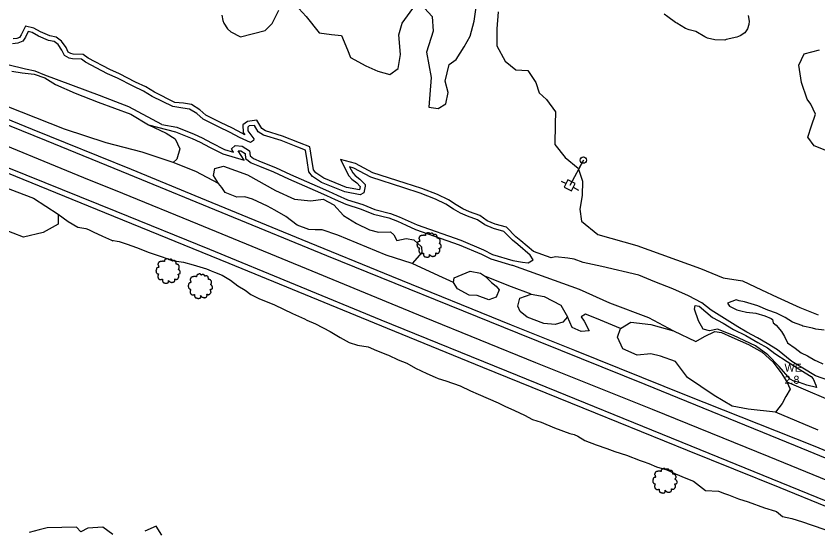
# Model space of a CAD drawing. Extents: x 2160437 to 2172832, y 205694 to 212444.
# Drawn here: x 2165285 to 2165786, y 209408 to 209730 of the extents above; entities that cross this region are included whole.
import ezdxf

# ---------------------------------------------------------------- set-up
doc = ezdxf.new("R2010")
doc.units = 0
for name, color, linetype in [('RD_EX_H2O', 7, 'Continuous'), ('RD_EX_H2O_Pond', 7, 'Continuous'), ('RD_EX_H2O_txCode', 7, 'Continuous'), ('RD_EX_LaneStripe', 7, 'Continuous'), ('RD_EX_Road', 7, 'Continuous'), ('RD_EX_UT', 7, 'Continuous'), ('RD_EX_UT_Guy', 7, 'Continuous'), ('RD_EX_VEG', 7, 'Continuous'), ('RD_EX_VEG_ShrubLine', 7, 'Continuous'), ('RD_EX_VEG_TreeLine', 7, 'Continuous')]:
    doc.layers.add(name, color=color, linetype=linetype)

# ---------------------------------------------------------------- blocks, each defined once
blk = doc.blocks.new('T2')
at = {"layer": 'RD_EX_VEG'}
for points in [[(0.05, 7.21), (-0.25, 7.24), (-0.57, 7.14), (-0.82, 7.04), (-1.05, 6.96), (-1.27, 6.86), (-1.57, 6.69), (-1.8, 6.49), (-1.92, 6.24), (-1.97, 6.01), (-2.02, 5.74), (-2.02, 5.56), (-2.15, 5.54), (-2.3, 5.56), (-2.55, 5.64), (-2.8, 5.64), (-3.05, 5.64), (-3.4, 5.61), (-3.75, 5.61), (-4.02, 5.56), (-4.35, 5.51), (-4.72, 5.39), (-5.07, 5.26), (-5.37, 5.01), (-5.62, 4.54), (-5.75, 4.19), (-5.9, 3.94), (-5.75, 3.49), (-5.57, 3.14), (-5.55, 2.94), (-5.47, 2.52), (-5.37, 2.29), (-5.25, 2.09), (-5.32, 2.07), (-5.7, 2.02), (-6, 1.92), (-6.42, 1.69), (-6.64, 1.47), (-6.74, 1.14), (-6.77, 0.79), (-6.87, 0.59), (-6.94, 0.32), (-6.97, 0.24), (-7.02, -0.08), (-6.92, -0.53), (-6.89, -0.88), (-6.77, -1.11), (-6.62, -1.28), (-6.44, -1.53), (-6.05, -1.76), (-5.72, -1.86), (-5.52, -1.88), (-5.7, -2.38), (-5.75, -2.73), (-5.87, -3.13), (-5.87, -3.21), (-5.92, -3.68), (-5.77, -4.01), (-5.7, -4.38), (-5.52, -4.61), (-5.25, -4.91), (-4.92, -5.13), (-4.42, -5.26), (-4.02, -5.23), (-3.45, -5.06), (-3.2, -4.98), (-3.22, -5.16), (-3.2, -5.53), (-3.2, -5.96), (-3.05, -6.28), (-2.95, -6.56), (-2.8, -6.81), (-2.47, -7.03), (-2.07, -7.11), (-1.65, -7.26), (-1.2, -7.33), (-0.7, -7.36), (-0.1, -7.21), (0.18, -7.08), (0.28, -6.91), (0.48, -6.53), (0.43, -6.31), (0.45, -5.71), (0.55, -5.88), (0.73, -6.23), (1.23, -6.53), (1.63, -6.71), (2.1, -6.86), (2.4, -6.93), (2.88, -6.86), (3.25, -6.78), (3.63, -6.66), (3.93, -6.38), (4.1, -6.11), (4.15, -5.83), (4.23, -5.46), (4.28, -5.28)], [(4.28, -5.28), (4.2, -5.11), (4.15, -4.86), (4.23, -4.88), (4.4, -4.93), (4.68, -5.06), (4.9, -5.13), (5.23, -5.11), (5.5, -5.01), (5.95, -4.73), (6.22, -4.26), (6.5, -3.86), (6.57, -3.53), (6.52, -3.31), (6.5, -2.81), (6.3, -2.56), (6.25, -2.43), (6.15, -2.03), (6.22, -1.98), (6.5, -1.93), (6.87, -1.81), (7.15, -1.68), (7.37, -1.51), (7.45, -1.28), (7.42, -0.88), (7.47, -0.48), (7.4, -0.33), (7.3, -0.18), (7.22, 0.02), (7.07, 0.17), (6.97, 0.32), (6.87, 0.42), (6.75, 0.57), (6.57, 0.69), (6.42, 0.74), (6.37, 0.89), (6.52, 1.09), (6.57, 1.19), (6.6, 1.42), (6.82, 1.77), (6.87, 2.17), (6.82, 2.59), (6.77, 2.87), (6.62, 3.14), (6.42, 3.39), (6.3, 3.56), (6.12, 3.69), (5.8, 3.81), (5.55, 3.86), (5.2, 3.86), (5, 3.91), (5.03, 3.96), (5.03, 4.11), (5.03, 4.39), (4.95, 4.84), (4.8, 5.34), (4.8, 5.36), (4.7, 5.61), (4.48, 5.81), (4.3, 5.91), (4.1, 6.04), (3.85, 6.06), (3.55, 6.06), (3.28, 6.01), (3.08, 5.91), (2.9, 5.79), (2.83, 5.94), (2.73, 6.24), (2.68, 6.39), (2.53, 6.56), (2.3, 6.76), (1.85, 6.89), (1.23, 6.81), (0.93, 6.61), (0.78, 6.44), (0.73, 6.56), (0.53, 6.76), (0.43, 6.94), (0.25, 7.06), (0.1, 7.16), (0, 7.21)]]:
    blk.add_spline(points, degree=3, dxfattribs=at)
blk = doc.blocks.new('PP')
at = {"layer": 'RD_EX_UT'}
for p, q in [((2.49, 2.51), (-2.51, 2.51)), ((-2.51, 2.51), (-2.51, -2.49)), ((2.49, -2.49), (2.49, 2.51)), ((-5.94, -0.05), (-2.47, -0.05)), ((-2.51, -2.49), (2.49, -2.49)), ((2.42, -0.05), (6.06, -0.05))]:
    blk.add_line(p, q, dxfattribs=at)

msp = doc.modelspace()

# ---------------------------------------------------------------- linework, layer by layer
at = {"layer": 'RD_EX_H2O'}
for points in [[(2165383.21, 209673.19), (2165370.29, 209679.52), (2165364.87, 209682.85), (2165358.5, 209685.91), (2165348.6, 209690.96), (2165342.47, 209693.62), (2165328.63, 209700.92), (2165326.12, 209702.91), (2165320.55, 209703.04), (2165318.44, 209703.55), (2165315.57, 209705.19), (2165313.96, 209708.57), (2165311.53, 209711.95), (2165309.1, 209713.84), (2165305.53, 209714.5), (2165299.28, 209717.18), (2165295.27, 209719.47), (2165292.87, 209720.08), (2165291.13, 209716.69), (2165289.58, 209714.02), (2165286.45, 209712.89), (2165283.09, 209712.55)], [(2165376.36, 209662.08), (2165355.65, 209673.06), (2165347.65, 209676.25), (2165337.34, 209680.16), (2165303.22, 209692.96), (2165297.17, 209695.4), (2165291.1, 209696.71), (2165280.11, 209699.37)], [(2165376.36, 209662.08), (2165385.62, 209660.32), (2165396.5, 209656.08), (2165401.61, 209653.67), (2165407.42, 209650.5), (2165415.52, 209646.44), (2165421.12, 209644.82), (2165420.11, 209646.45), (2165419.78, 209646.92), (2165422.09, 209648.84), (2165426.52, 209648.5), (2165431.17, 209645.67), (2165431.43, 209642.37), (2165433.62, 209640.76), (2165438.4, 209638.73), (2165447.29, 209635.23), (2165456.69, 209630.73), (2165473.41, 209623.58), (2165480.41, 209620.42), (2165485.75, 209617.82), (2165492.31, 209614.99), (2165501.79, 209612), (2165509.44, 209608.97), (2165519.06, 209606.51), (2165524.64, 209604.35), (2165530.19, 209601.79), (2165535.87, 209599.26), (2165563.11, 209589.7), (2165577.29, 209583.8), (2165582.91, 209580.9), (2165595.64, 209577.06), (2165601.64, 209575.94), (2165605.02, 209575.66), (2165608.17, 209577.53), (2165606.29, 209580.46), (2165598.59, 209586.97), (2165595.31, 209589.7), (2165590.01, 209595.14), (2165583.51, 209596.98), (2165577.95, 209599.28), (2165573.45, 209602.55), (2165567.29, 209604.74), (2165562.93, 209606.68), (2165558.5, 209609.19), (2165553.79, 209612.28), (2165547.22, 209615.48), (2165537.61, 209619.11), (2165527.37, 209622.44), (2165506.92, 209629.07), (2165496.22, 209634.83), (2165493.57, 209635.51), (2165495.52, 209631.74), (2165497.01, 209630.17), (2165500.01, 209627.83), (2165503.38, 209624.47), (2165503.41, 209623.51), (2165502.46, 209619.25), (2165500.27, 209617.99), (2165490.71, 209619.88), (2165476.09, 209625.83), (2165470.37, 209629.51), (2165468.17, 209632.54), (2165467.1, 209639.64), (2165466.08, 209645.92), (2165461.28, 209647.91), (2165450.8, 209652.02), (2165439.87, 209655.43), (2165436.58, 209657.44), (2165434.11, 209661.49), (2165430.95, 209661.12), (2165429.96, 209660.42), (2165430.14, 209658.07), (2165433.79, 209653), (2165433.58, 209652), (2165431.7, 209650.75), (2165424.87, 209653.87), (2165419.09, 209657.12), (2165411.68, 209660.6), (2165402.1, 209665.31), (2165398.17, 209668.83), (2165393.71, 209671.67), (2165389.37, 209672.33), (2165383.21, 209673.19)]]:
    msp.add_lwpolyline(points, dxfattribs=at)
at = {"layer": 'RD_EX_H2O_Pond'}
msp.add_lwpolyline([(2165768.77, 209502.88), (2165761.78, 209510.76), (2165754.88, 209518.14), (2165747.12, 209523.77), (2165733.39, 209530.1), (2165723.32, 209534.12), (2165718.28, 209533.09), (2165714.35, 209534.06), (2165711.58, 209539.38), (2165709.08, 209546.63), (2165709.42, 209548.93), (2165711.93, 209548.45), (2165720.24, 209541.49), (2165726.87, 209537.9), (2165733.4, 209534), (2165740.95, 209530.14), (2165748.47, 209525.8), (2165754.62, 209522.57), (2165759.26, 209519), (2165766.77, 209514.03), (2165775.39, 209508.57), (2165781.75, 209504.6), (2165783.09, 209503.1), (2165784.83, 209499.05), (2165785.27, 209497.68), (2165779.14, 209499.22), (2165774.54, 209500.72), (2165771.03, 209501.74)], close=True, dxfattribs=at)
at = {"layer": 'RD_EX_LaneStripe'}
for points in [[(2164713.96, 209878.5), (2164761.8, 209859.02), (2164833.01, 209830.23), (2164905.18, 209800.77), (2164974.57, 209772.6), (2165045.57, 209743.73), (2165114.59, 209715.4), (2165186.42, 209686.18), (2165257.45, 209657.65), (2165327.49, 209628.98), (2165351.71, 209619.17)], [(2165351.71, 209619.17), (2165398.66, 209599.89), (2165469.92, 209570.6), (2165540.18, 209541.69), (2165609.74, 209513.4), (2165682.5, 209484.08), (2165755.38, 209454.5), (2165825.21, 209425.99), (2165895.04, 209397.29), (2165966.21, 209368.17), (2166025.36, 209344.25)]]:
    msp.add_lwpolyline(points, dxfattribs=at)
at = {"layer": 'RD_EX_Road'}
for points in [[(2164719.32, 209893.53), (2164801.13, 209860.4), (2164852.34, 209839.67), (2164925.53, 209809.88), (2165006.4, 209777.19), (2165079.44, 209747.05), (2165147.78, 209719.5), (2165223.63, 209688.47), (2165295.33, 209659.22), (2165357.09, 209634.04)], [(2165355.66, 209630.84), (2165304.42, 209651.77), (2165236.8, 209679.06), (2165166.59, 209707.41), (2165107.77, 209731.24), (2165033.8, 209761.44), (2164971.08, 209787.01), (2164897.12, 209817.11), (2164827.21, 209845.74), (2164717.47, 209890.02)], [(2165346.3, 209604.56), (2165269.06, 209635.97), (2165210.92, 209659.39), (2165137.15, 209689.5), (2165059.95, 209721.27), (2164996.92, 209746.76), (2164929.74, 209773.98), (2164862.92, 209800.29), (2164815.46, 209819.83), (2164749.27, 209847.18), (2164706.89, 209864.18)], [(2164708.26, 209867.65), (2164791.22, 209833.73), (2164881.75, 209797.03), (2164973.9, 209759.85), (2165049.76, 209728.91), (2165135.66, 209693.84), (2165203.67, 209666.14), (2165280.55, 209635.01), (2165347.69, 209607.9)], [(2165357.09, 209634.04), (2165400.48, 209616.17), (2165463.79, 209590.16), (2165519.82, 209567.3), (2165594.5, 209536.83), (2165634.04, 209521.03), (2165703.73, 209492.82), (2165783.1, 209461.45), (2165877.48, 209422.45), (2165937.8, 209397.18), (2165998.2, 209372.29), (2166026.17, 209360.72)], [(2166024.71, 209357.76), (2165943.48, 209390.77), (2165859.72, 209425.24), (2165772.07, 209461.29), (2165678.08, 209499.62), (2165598.61, 209531.58), (2165479.36, 209579.95), (2165355.66, 209630.84)], [(2165347.69, 209607.9), (2165406.01, 209584.16), (2165513.05, 209539.94), (2165598.18, 209505.37), (2165706.73, 209461.26), (2165813.54, 209417.73), (2165902.46, 209381.16), (2166015.83, 209334.81)], [(2166014.65, 209331.72), (2165949.69, 209358.32), (2165878.21, 209387.6), (2165819.58, 209411.66), (2165762.4, 209434.9), (2165704.62, 209458.26), (2165647.21, 209481.6), (2165576.85, 209510.24), (2165517.3, 209534.48), (2165418.35, 209575.15), (2165346.3, 209604.56)]]:
    msp.add_lwpolyline(points, dxfattribs=at)
at = {"layer": 'RD_EX_UT'}
msp.add_line((2165639.58, 209639.79), (2165637.26, 209635.36), dxfattribs=at)
msp.add_circle((2165639.58, 209639.79), 2, dxfattribs=at)
at = {"layer": 'RD_EX_UT_Guy'}
msp.add_lwpolyline([(2165639.58, 209639.79), (2165631.1, 209623.97)], dxfattribs=at)
at = {"layer": 'RD_EX_VEG_ShrubLine'}
for points in [[(2165413.87, 209730.4), (2165414.42, 209727.04), (2165414.96, 209725.3), (2165417.33, 209721.86), (2165419.36, 209719.94), (2165425.49, 209716.74), (2165425.49, 209716.74), (2165440.97, 209720.85), (2165445.27, 209725.21), (2165449.35, 209733.57)], [(2165459.57, 209736.93), (2165466.52, 209729.48), (2165474.53, 209719.29), (2165482.38, 209718.34), (2165488.58, 209717.59), (2165492.22, 209708.61), (2165494.25, 209703.98), (2165503.71, 209698.69), (2165511.3, 209695.31), (2165518.83, 209693.24), (2165524, 209697.12), (2165525.32, 209705.8), (2165524.31, 209718.06), (2165526.4, 209725.4), (2165533.04, 209734.62)], [(2165540.39, 209734.8), (2165545.09, 209729.63), (2165545.73, 209720.44), (2165541.53, 209707.32), (2165544.55, 209691.44), (2165543.16, 209672.97), (2165548.89, 209671.97), (2165553.63, 209674.86), (2165555.16, 209681.99), (2165553.32, 209689.08), (2165555.75, 209699.45), (2165560.1, 209702.7), (2165565.16, 209710.62), (2165568.99, 209717.19), (2165571.35, 209726.58), (2165572.85, 209736.91)], [(2165586.36, 209732.54), (2165585.55, 209721.73), (2165585.54, 209711.28), (2165590.73, 209701.71), (2165597.41, 209696.29), (2165604.9, 209695.77), (2165609.92, 209688.27), (2165612.07, 209681.86), (2165616.65, 209677.65), (2165622.09, 209669.87), (2165621.99, 209662.28), (2165621.79, 209649.56), (2165628.29, 209641.5), (2165636.25, 209634.68), (2165639.04, 209626.63), (2165638.93, 209617.6), (2165637.42, 209609.09), (2165638.43, 209601.55), (2165648.54, 209593.24), (2165672.94, 209586.4), (2165712.72, 209572.07), (2165726.93, 209566.22), (2165738.98, 209564.31), (2165750.76, 209558.71), (2165760.66, 209554.22), (2165774.75, 209547.68), (2165786.14, 209543.07)], [(2165742.46, 209730.18), (2165743.03, 209726.56), (2165742.83, 209724.47), (2165742.05, 209721.91), (2165740.35, 209719.3), (2165737.5, 209717.39), (2165735.53, 209716.63), (2165728.83, 209715.06), (2165727.85, 209714.68), (2165721.74, 209714.85), (2165717.08, 209716.02), (2165715.52, 209716.8), (2165709.8, 209720.07), (2165705.74, 209721.15), (2165703.39, 209722.01), (2165697.86, 209725.29), (2165697.05, 209725.74), (2165692.44, 209729.24), (2165689.97, 209731.06)], [(2165384.53, 209675.88), (2165371.73, 209682.15), (2165366.31, 209685.48), (2165359.83, 209688.6), (2165349.88, 209693.67), (2165343.77, 209696.32), (2165330.28, 209703.45), (2165327.2, 209705.88), (2165320.95, 209706.03), (2165319.56, 209706.37), (2165317.87, 209707.33), (2165316.55, 209710.1), (2165313.71, 209714.06), (2165310.36, 209716.66), (2165306.4, 209717.39), (2165300.62, 209719.86), (2165296.4, 209722.27), (2165291.3, 209723.58), (2165288.49, 209718.13), (2165287.54, 209716.47), (2165285.78, 209715.84), (2165283.44, 209715.6)], [(2165790.5, 209646.07), (2165783.8, 209648.78), (2165779.8, 209654.1), (2165782.01, 209661.11), (2165784.61, 209668.59), (2165781.57, 209674.84), (2165779.39, 209677.9), (2165779.39, 209677.9), (2165775.76, 209688.33), (2165774.22, 209699.19), (2165777.51, 209706.18), (2165787.06, 209708.65)], [(2165805.27, 209497.64), (2165784.63, 209505.04), (2165769.85, 209514.02), (2165760.79, 209521.13), (2165754.44, 209525.14), (2165748.35, 209528.8), (2165741.63, 209532.29), (2165735.98, 209535.62), (2165719.45, 209545.96), (2165713.57, 209550.53), (2165705.31, 209554.93), (2165695.53, 209559.41), (2165684.24, 209563.75), (2165674.2, 209567.84), (2165651.19, 209573.3), (2165639.42, 209575.85), (2165633.86, 209577.96), (2165629.97, 209578.6), (2165622.22, 209579.27), (2165619.39, 209578.72), (2165608.36, 209582.63), (2165600.52, 209589.26), (2165597.35, 209591.9), (2165591.6, 209597.81), (2165584.5, 209599.82), (2165579.42, 209601.91), (2165574.86, 209605.23), (2165568.41, 209607.53), (2165564.28, 209609.36), (2165560.07, 209611.75), (2165555.28, 209614.9), (2165548.41, 209618.24), (2165538.61, 209621.95), (2165528.3, 209625.29), (2165508.11, 209631.84), (2165497.32, 209637.65), (2165487.83, 209640.08), (2165493.05, 209629.98), (2165494.98, 209627.94), (2165498.02, 209625.58), (2165500.29, 209623.32), (2165499.82, 209621.19), (2165499.76, 209621.15), (2165491.57, 209622.77), (2165477.48, 209628.51), (2165472.46, 209631.74), (2165471.03, 209633.71), (2165470.07, 209640.11), (2165468.77, 209648.04), (2165462.41, 209650.69), (2165451.8, 209654.85), (2165441.12, 209658.18), (2165438.76, 209659.62), (2165435.67, 209664.69), (2165429.85, 209664.01), (2165426.84, 209661.9), (2165427.21, 209657), (2165428.18, 209655.66), (2165426.23, 209656.55), (2165420.46, 209659.79), (2165412.98, 209663.3), (2165403.8, 209667.82), (2165399.99, 209671.23), (2165394.79, 209674.54), (2165389.8, 209675.3), (2165384.53, 209675.88)], [(2165368.02, 209661.84), (2165384.79, 209657.43), (2165395.32, 209653.32), (2165400.25, 209651), (2165406.03, 209647.84), (2165414.42, 209643.64), (2165427.75, 209639.77), (2165424.11, 209645.68), (2165425.58, 209645.57), (2165428.3, 209643.91), (2165428.55, 209640.77), (2165432.13, 209638.14), (2165437.26, 209635.95), (2165446.09, 209632.48), (2165455.45, 209628), (2165472.2, 209620.83), (2165479.14, 209617.7), (2165484.5, 209615.09), (2165491.26, 209612.18), (2165500.78, 209609.18), (2165508.51, 209606.11), (2165518.15, 209603.65), (2165523.47, 209601.58), (2165528.95, 209599.06), (2165534.77, 209596.47), (2165562.03, 209586.9), (2165576.02, 209581.08), (2165581.77, 209578.11), (2165594.93, 209574.14), (2165595.27, 209574.07), (2165636.93, 209559.05), (2165655.82, 209550.56), (2165680.17, 209541.47), (2165695.89, 209533.1)], [(2165411.78, 209625.18), (2165397.56, 209632.71), (2165383.48, 209638.33)], [(2165311.58, 209606.05), (2165317.82, 209601.48), (2165323.88, 209597.83), (2165328.8, 209597.03), (2165330.52, 209596.45), (2165333.48, 209595.02), (2165339.2, 209592.24), (2165344.83, 209589.8), (2165345.81, 209589.31)], [(2165344.83, 209589.8), (2165344.83, 209589.8), (2165349.77, 209588.93), (2165354.59, 209587.29), (2165360.61, 209585.2), (2165368.47, 209582.03), (2165376.03, 209579.53), (2165379.49, 209578.31), (2165382.62, 209576.97), (2165389.95, 209575.98), (2165396.01, 209574.28), (2165404.21, 209571.78), (2165407.08, 209570.59), (2165409.24, 209569.72), (2165414.1, 209567.88), (2165419.3, 209564.75), (2165423.81, 209561.29), (2165428.4, 209558.44), (2165431.91, 209555.82), (2165436.95, 209553.36), (2165446.73, 209549.29), (2165457.97, 209544.02), (2165465.43, 209540.56), (2165466.8, 209539.87), (2165472.3, 209537.42), (2165481.47, 209532.61), (2165487.62, 209528.97), (2165493.27, 209525.83), (2165498.44, 209524.17), (2165505.23, 209523.1), (2165510.41, 209520.84), (2165517.31, 209518.19), (2165517.86, 209517.89), (2165523.83, 209515.06), (2165529.39, 209512.86), (2165534.82, 209509.85), (2165541.73, 209506.38), (2165547.14, 209504.25), (2165548.95, 209503.3), (2165553.79, 209501.83), (2165562.58, 209498.7), (2165569.16, 209495.64), (2165573.8, 209493.49), (2165580.22, 209490.77), (2165586.44, 209488.09), (2165590.57, 209485.94), (2165596.51, 209483.25), (2165602.77, 209480.47), (2165607.82, 209477.64), (2165613.28, 209476.12), (2165621.56, 209472.57), (2165631.05, 209468.99), (2165633.93, 209468.3), (2165636.22, 209467.24), (2165640.54, 209464.68), (2165647.67, 209461.92), (2165654.29, 209459.53), (2165659.2, 209457.8), (2165666.46, 209455.34), (2165675.09, 209452.05), (2165677.01, 209451.47), (2165680.56, 209450.16), (2165685.24, 209448.22), (2165691.63, 209446.34), (2165697.17, 209443.78), (2165703.61, 209441.1), (2165708.39, 209439.07), (2165715.86, 209433.29), (2165723.98, 209432.96), (2165727.8, 209431.44), (2165730.29, 209430.7), (2165736.4, 209428.21), (2165742.41, 209426.17), (2165752.63, 209422.4), (2165759.58, 209420.35), (2165760.16, 209420.23), (2165764.04, 209417.1), (2165769.84, 209415.75), (2165776.35, 209413.72), (2165781.86, 209411.81), (2165790.96, 209408.68)], [(2165558.42, 209563.23), (2165549.34, 209567.44), (2165532.75, 209575.18)], [(2165606.97, 209555.96), (2165594.81, 209560.68), (2165578.57, 209567.08)], [(2165790, 209533.45), (2165784.8, 209534.22), (2165782.69, 209534.79), (2165776.65, 209536.11), (2165775.96, 209536.42), (2165770.25, 209538.5), (2165770.25, 209538.5), (2165765.69, 209541.53), (2165760.19, 209544.06), (2165754.82, 209546.09), (2165748.5, 209548.63), (2165740.2, 209551.22), (2165736.79, 209551.92), (2165735.09, 209552.4), (2165729.68, 209550.45), (2165730.92, 209548.53), (2165730.92, 209548.53), (2165735.52, 209546.22), (2165737.93, 209545.69), (2165741.42, 209544.77), (2165747.25, 209544.18), (2165747.25, 209544.18), (2165752.86, 209542.51), (2165756.84, 209540.83), (2165757.8, 209540.13), (2165758.19, 209538.14), (2165759.9, 209536.66), (2165763.27, 209532.79), (2165765.23, 209529.65), (2165767.16, 209525.61), (2165771.85, 209522.26), (2165775.69, 209519.46), (2165779.61, 209517.44), (2165784.08, 209514.82), (2165785.6, 209514.15), (2165789.16, 209512.56)], [(2165662.76, 209534.61), (2165647.88, 209540.86), (2165641.01, 209543.6), (2165638.19, 209541.85), (2165640.02, 209539.13), (2165643.27, 209533.05), (2165638.26, 209532.73), (2165632.65, 209535.23), (2165629.62, 209541.8)], [(2165766.6, 209501.26), (2165802.67, 209485.82)], [(2165786.28, 209471.03), (2165759.49, 209482.3)], [(2165345.82, 209405.85), (2165339.48, 209410.46), (2165330.21, 209409.88), (2165325.77, 209407.44), (2165323.08, 209410.35), (2165304.65, 209409.95), (2165299.84, 209408.75), (2165293.59, 209407.04)], [(2165376.44, 209405.49), (2165372.7, 209410.95), (2165365.69, 209407.89)]]:
    msp.add_lwpolyline(points, dxfattribs=at)
for points in [[(2165442.38, 209610.94), (2165433.04, 209615.37), (2165428.21, 209616.79), (2165423.26, 209616.58), (2165415.92, 209619.57), (2165413.91, 209622.73), (2165411.78, 209625.18), (2165408.67, 209630.15), (2165409.5, 209634.46), (2165414.78, 209635.93), (2165429.8, 209630.57), (2165447.4, 209620.8), (2165459.23, 209615.31), (2165469.48, 209614.25), (2165477.12, 209615.31), (2165483.8, 209611.84), (2165489.85, 209605.11), (2165497.88, 209600.18), (2165506.11, 209596.2), (2165511.68, 209594.73), (2165519.08, 209595.02), (2165521.14, 209593.02), (2165523.06, 209589.57), (2165528.99, 209590.75), (2165533.67, 209590.04), (2165538.59, 209585.67), (2165538.75, 209582.05), (2165532.75, 209575.18), (2165516.44, 209580.3), (2165486.2, 209592.92), (2165476.46, 209596.25), (2165472.01, 209596.14), (2165468.22, 209596.41), (2165460.78, 209599.08), (2165453.73, 209604.49), (2165446.84, 209608.51)], [(2165558.98, 209566.25), (2165568.81, 209570.37), (2165575.35, 209569.24), (2165578.57, 209567.08), (2165582.25, 209563.4), (2165585.13, 209561.08), (2165587.07, 209558.81), (2165585.1, 209554.18), (2165580.46, 209552.52), (2165573.24, 209555.09), (2165568.37, 209555.49), (2165561.08, 209559.32), (2165558.42, 209563.23)], [(2165598.6, 209548.46), (2165600, 209553.47), (2165606.97, 209555.96), (2165615.15, 209554.64), (2165625.51, 209549.22), (2165629.62, 209541.8), (2165626.7, 209538.51), (2165622.05, 209537.03), (2165614.98, 209537.68), (2165604.39, 209541.66), (2165600.13, 209545.27)], [(2165759.49, 209482.3), (2165742.51, 209484.26), (2165732.54, 209486.06), (2165721.28, 209492.61), (2165704.58, 209503.89), (2165697.1, 209513.94), (2165687.76, 209517.36), (2165681.81, 209518.78), (2165673.11, 209517.93), (2165664.27, 209521.95), (2165660.93, 209529.25), (2165662.76, 209534.61), (2165669.3, 209538.47), (2165681.66, 209537.16), (2165695.89, 209533.1), (2165709.89, 209526.47), (2165715.3, 209529.65), (2165721.72, 209532.75), (2165725.77, 209532.14), (2165732.27, 209529.2), (2165742.67, 209524.48), (2165751.35, 209519.68), (2165757.88, 209513.82), (2165763.02, 209506.9), (2165766.6, 209501.26), (2165768.64, 209496.64), (2165765.94, 209492.11), (2165763.69, 209487.75)]]:
    msp.add_lwpolyline(points, close=True, dxfattribs=at)
at = {"layer": 'RD_EX_VEG_TreeLine'}
msp.add_lwpolyline([(2165282.62, 209695.34), (2165289.21, 209694.39), (2165296.56, 209693.53), (2165303.29, 209691.15), (2165309.91, 209687.14), (2165322.22, 209681.67), (2165336.68, 209676.04), (2165356.97, 209668.42), (2165368.02, 209661.84), (2165378.98, 209656.56), (2165384.75, 209653.1), (2165387.57, 209646.88), (2165385.74, 209640.32), (2165383.48, 209638.33), (2165364, 209644.69), (2165341.52, 209650.59), (2165315.54, 209659.17), (2165252.77, 209683.83)], dxfattribs=at)
msp.add_lwpolyline([(2165228.2, 209635.35), (2165240.38, 209636.06), (2165262.12, 209629), (2165296.16, 209616), (2165311.58, 209606.05), (2165311.67, 209599.77), (2165302.15, 209594.52), (2165290.02, 209591.63), (2165263.86, 209601.56), (2165235, 209615.01), (2165229.11, 209623.2)], close=True, dxfattribs=at)

# ---------------------------------------------------------------- block references
at = {"layer": 'RD_EX_UT', "xscale": 1.0199999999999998, "yscale": 1.0199999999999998, "rotation": -27.159763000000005}
msp.add_blockref('PP', (2165631.1, 209623.97), dxfattribs=at)
at = {"layer": 'RD_EX_VEG', "xscale": 1.0499999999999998, "yscale": 1.0499999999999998}
for p in [(2165543.04, 209586.87), (2165380.05, 209570.62), (2165400.17, 209561.09), (2165690.26, 209439.48)]:
    msp.add_blockref('T2', p, dxfattribs=at)

# ---------------------------------------------------------------- texts
at = {"layer": 'RD_EX_H2O_txCode'}
for s, p in [('WE', (2165765.22, 209507.52)), ('2.8', (2165765.22, 209500.02))]:
    msp.add_text(s, height=5, dxfattribs=at).set_placement(p)

doc.saveas('drawing.dxf')
